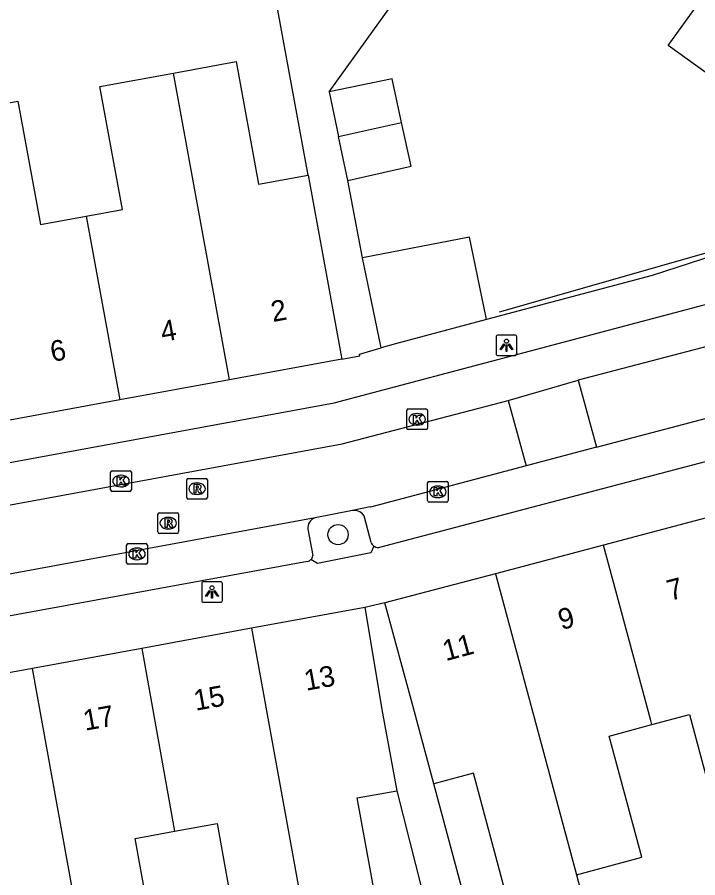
# Model space of a CAD drawing. Extents: x 159718 to 160783, y 383290 to 384030.
# Drawn here: x 160296.37 to 160329.24, y 383658.33 to 383699.92 of the extents above; entities that cross this region are included whole.
import ezdxf

# ---------------------------------------------------------------- set-up
doc = ezdxf.new("R2010")
doc.units = 0
for name, color, linetype in [('IMGEO_Boom', 7, 'Continuous'), ('IMGEO_Kolk', 7, 'Continuous'), ('IMGEO_Lichtpunt', 7, 'Continuous'), ('IMGEO_Muur', 7, 'Continuous'), ('IMGEO_Pand', 7, 'Continuous'), ('IMGEO_Pand_nummerreeks', 7, 'Continuous'), ('IMGEO_Parkeervlak_open', 7, 'Continuous'), ('IMGEO_Rijbaan_lokaal_open', 7, 'Continuous'), ('IMGEO_Rioolput', 7, 'Continuous'), ('IMGEO_Voetpad_open', 7, 'Continuous')]:
    doc.layers.add(name, color=color, linetype=linetype)

msp = doc.modelspace()

# ---------------------------------------------------------------- linework, layer by layer
at = {"layer": 'IMGEO_Boom'}
msp.add_circle((160311.869, 383674.911), 0.489, dxfattribs=at)
at = {"layer": 'IMGEO_Kolk'}
for p, q in [((160315.187, 383680.059), (160315.187, 383680.911)), ((160315.262, 383680.985), (160316.114, 383680.985)), ((160316.188, 383680.911), (160316.188, 383680.059)), ((160315.675, 383680.765), (160315.7, 383680.765)), ((160316.114, 383679.985), (160315.262, 383679.985)), ((160315.698, 383680.205), (160315.673, 383680.205)), ((160300.885, 383677.074), (160300.885, 383677.926)), ((160300.96, 383678), (160301.812, 383678)), ((160301.886, 383677.926), (160301.886, 383677.074)), ((160301.373, 383677.78), (160301.398, 383677.78)), ((160301.396, 383677.22), (160301.371, 383677.22)), ((160316.191, 383676.556), (160316.191, 383677.408)), ((160316.266, 383677.482), (160317.118, 383677.482)), ((160316.679, 383677.262), (160316.704, 383677.262)), ((160317.192, 383677.408), (160317.192, 383676.556)), ((160301.812, 383677), (160300.96, 383677)), ((160316.702, 383676.702), (160316.677, 383676.702)), ((160317.118, 383676.482), (160316.266, 383676.482)), ((160301.657, 383673.555), (160301.657, 383674.407)), ((160301.732, 383674.481), (160302.584, 383674.481)), ((160302.145, 383674.261), (160302.17, 383674.261)), ((160302.658, 383674.407), (160302.658, 383673.555)), ((160302.584, 383673.481), (160301.732, 383673.481)), ((160302.168, 383673.701), (160302.143, 383673.701))]:
    msp.add_line(p, q, dxfattribs=at)
for points in [[(160315.187, 383680.059), (160315.187, 383680.911)], [(160315.262, 383680.985), (160316.114, 383680.985)], [(160316.188, 383680.911), (160316.188, 383680.059)], [(160315.508, 383680.685), (160315.631, 383680.685), (160315.631, 383680.534), (160315.761, 383680.685), (160315.925, 383680.685), (160315.779, 383680.534), (160315.932, 383680.285), (160315.78, 383680.285), (160315.695, 383680.449), (160315.631, 383680.382), (160315.631, 383680.285), (160315.508, 383680.285), (160315.508, 383680.685)], [(160316.114, 383679.985), (160315.262, 383679.985)], [(160300.885, 383677.074), (160300.885, 383677.926)], [(160300.96, 383678), (160301.812, 383678)], [(160301.886, 383677.926), (160301.886, 383677.074)], [(160301.206, 383677.7), (160301.329, 383677.7), (160301.329, 383677.549), (160301.459, 383677.7), (160301.623, 383677.7), (160301.477, 383677.549), (160301.63, 383677.3), (160301.478, 383677.3), (160301.393, 383677.464), (160301.329, 383677.397), (160301.329, 383677.3), (160301.206, 383677.3), (160301.206, 383677.7)], [(160316.191, 383676.556), (160316.191, 383677.408)], [(160316.266, 383677.482), (160317.118, 383677.482)], [(160316.512, 383677.182), (160316.635, 383677.182), (160316.635, 383677.031), (160316.765, 383677.182), (160316.929, 383677.182), (160316.783, 383677.031), (160316.936, 383676.782), (160316.784, 383676.782), (160316.699, 383676.946), (160316.635, 383676.879), (160316.635, 383676.782), (160316.512, 383676.782), (160316.512, 383677.182)], [(160317.192, 383677.408), (160317.192, 383676.556)], [(160301.812, 383677), (160300.96, 383677)], [(160317.118, 383676.482), (160316.266, 383676.482)], [(160301.657, 383673.555), (160301.657, 383674.407)], [(160301.732, 383674.481), (160302.584, 383674.481)], [(160301.978, 383674.181), (160302.101, 383674.181), (160302.101, 383674.03), (160302.231, 383674.181), (160302.395, 383674.181), (160302.249, 383674.03), (160302.402, 383673.781), (160302.25, 383673.781), (160302.165, 383673.945), (160302.101, 383673.878), (160302.101, 383673.781), (160301.978, 383673.781), (160301.978, 383674.181)], [(160302.658, 383674.407), (160302.658, 383673.555)], [(160302.584, 383673.481), (160301.732, 383673.481)]]:
    msp.add_lwpolyline(points, dxfattribs=at)
for centre, start, end in [((160315.264, 383680.909), 91.552, 178.448), ((160315.264, 383680.909), 91.552, 178.448), ((160316.112, 383680.909), 1.552, 88.448), ((160316.112, 383680.909), 1.552, 88.448), ((160315.264, 383680.061), 181.552, 268.448), ((160315.264, 383680.061), 181.552, 268.448), ((160316.112, 383680.061), 271.552, 358.448), ((160316.112, 383680.061), 271.552, 358.448), ((160300.962, 383677.924), 91.552, 178.448), ((160300.962, 383677.924), 91.552, 178.448), ((160301.81, 383677.924), 1.552, 88.448), ((160301.81, 383677.924), 1.552, 88.448), ((160300.962, 383677.076), 181.552, 268.448), ((160300.962, 383677.076), 181.552, 268.448), ((160301.81, 383677.076), 271.552, 358.448), ((160301.81, 383677.076), 271.552, 358.448), ((160316.268, 383677.406), 91.552, 178.448), ((160316.268, 383677.406), 91.552, 178.448), ((160317.116, 383677.406), 1.552, 88.448), ((160317.116, 383677.406), 1.552, 88.448), ((160316.268, 383676.558), 181.552, 268.448), ((160316.268, 383676.558), 181.552, 268.448), ((160317.116, 383676.558), 271.552, 358.448), ((160317.116, 383676.558), 271.552, 358.448), ((160301.734, 383674.405), 91.552, 178.448), ((160301.734, 383674.405), 91.552, 178.448), ((160302.582, 383674.405), 1.552, 88.448), ((160302.582, 383674.405), 1.552, 88.448), ((160301.734, 383673.557), 181.552, 268.448), ((160301.734, 383673.557), 181.552, 268.448), ((160302.582, 383673.557), 271.552, 358.448), ((160302.582, 383673.557), 271.552, 358.448)]:
    msp.add_arc(centre, 0.0765, start, end, dxfattribs=at)
for centre, major_axis, ratio, start_param, end_param in [((160315.674, 383680.485), (-0.387, 0.002), 0.722429, 4.712389, 7.853982), ((160315.699, 383680.485), (-0.39, 0.002), 0.717154, 1.570796, 4.712389), ((160301.372, 383677.5), (-0.387, 0.002), 0.722429, 4.712389, 7.853982), ((160301.397, 383677.5), (-0.39, 0.002), 0.717154, 1.570796, 4.712389), ((160316.678, 383676.982), (-0.387, 0.002), 0.722429, 4.712389, 7.853982), ((160316.703, 383676.982), (-0.39, 0.002), 0.717154, 1.570796, 4.712389), ((160302.144, 383673.981), (-0.387, 0.002), 0.722429, 4.712389, 7.853982), ((160302.169, 383673.981), (-0.39, 0.002), 0.717154, 1.570796, 4.712389)]:
    msp.add_ellipse(centre, major_axis=major_axis, ratio=ratio, start_param=start_param, end_param=end_param, dxfattribs=at)
at = {"layer": 'IMGEO_Lichtpunt'}
for p, q in [((160320.408, 383684.558), (160319.6, 383684.558)), ((160320.408, 383684.558), (160319.6, 383684.558)), ((160319.506, 383684.463), (160319.506, 383683.656)), ((160319.506, 383684.463), (160319.506, 383683.656)), ((160320.502, 383683.656), (160320.502, 383684.463)), ((160320.502, 383683.656), (160320.502, 383684.463)), ((160319.6, 383683.562), (160320.408, 383683.562)), ((160319.6, 383683.562), (160320.408, 383683.562)), ((160305.285, 383672.544), (160305.285, 383671.737)), ((160305.285, 383672.544), (160305.285, 383671.737)), ((160306.187, 383672.639), (160305.379, 383672.639)), ((160306.187, 383672.639), (160305.379, 383672.639)), ((160306.281, 383671.737), (160306.281, 383672.544)), ((160306.281, 383671.737), (160306.281, 383672.544)), ((160305.379, 383671.643), (160306.187, 383671.643)), ((160305.379, 383671.643), (160306.187, 383671.643))]:
    msp.add_line(p, q, dxfattribs=at)
for points in [[(160319.88, 383684.127), (160319.919, 383684.099), (160319.731, 383683.837), (160319.693, 383683.864), (160319.88, 383684.127)], [(160319.982, 383684.079), (160320.029, 383684.079), (160320.029, 383683.757), (160319.982, 383683.757), (160319.982, 383684.079)], [(160320.092, 383684.099), (160320.13, 383684.126), (160320.317, 383683.864), (160320.278, 383683.836), (160320.092, 383684.099)], [(160305.659, 383672.208), (160305.698, 383672.18), (160305.51, 383671.918), (160305.472, 383671.945), (160305.659, 383672.208)], [(160305.761, 383672.16), (160305.808, 383672.16), (160305.808, 383671.838), (160305.761, 383671.838), (160305.761, 383672.16)], [(160305.871, 383672.18), (160305.909, 383672.207), (160306.096, 383671.945), (160306.057, 383671.917), (160305.871, 383672.18)]]:
    msp.add_lwpolyline(points, dxfattribs=at)
for centre in [(160320.005, 383684.261), (160305.784, 383672.342)]:
    msp.add_circle(centre, 0.0994, dxfattribs=at)
for centre, start, end in [((160319.6, 383684.463), 90, 180), ((160319.6, 383684.463), 90, 180), ((160320.408, 383684.463), 0, 90), ((160320.408, 383684.463), 0, 90), ((160319.6, 383683.656), 180, 270), ((160319.6, 383683.656), 180, 270), ((160320.408, 383683.656), 270, 0), ((160320.408, 383683.656), 270, 360), ((160305.379, 383672.544), 90, 180), ((160305.379, 383672.544), 90, 180), ((160306.187, 383672.544), 0, 90), ((160306.187, 383672.544), 0, 90), ((160305.379, 383671.737), 180, 270), ((160305.379, 383671.737), 180, 270), ((160306.187, 383671.737), 270, 0), ((160306.187, 383671.737), 270, 360)]:
    msp.add_arc(centre, 0.0946, start, end, dxfattribs=at)
at = {"layer": 'IMGEO_Muur'}
msp.add_lwpolyline([(160330.189, 383688.675), (160319.647, 383685.659)], dxfattribs=at)
at = {"layer": 'IMGEO_Pand'}
for points in [[(160330.562, 383696.566), (160327.807, 383698.555), (160331.167, 383703.206), (160329.688, 383704.274)], [(160303.92, 383697.218), (160306.948, 383697.772), (160308.033, 383691.84), (160310.427, 383692.278)], [(160299.702, 383690.309), (160301.457, 383690.63), (160300.37, 383696.568), (160303.92, 383697.218)], [(160306.633, 383682.393), (160303.92, 383697.218)], [(160314.94, 383694.825), (160314.477, 383696.939), (160311.443, 383696.314)], [(160311.443, 383696.314), (160311.892, 383694.157)], [(160293.306, 383695.296), (160296.401, 383695.862), (160297.492, 383689.904), (160299.702, 383690.309)], [(160311.892, 383694.157), (160314.94, 383694.825)], [(160312.335, 383692.03), (160315.403, 383692.711), (160314.94, 383694.825)], [(160312.335, 383692.03), (160311.892, 383694.157)], [(160310.427, 383692.278), (160311.153, 383688.319), (160312.009, 383683.641), (160312.056, 383683.385)], [(160299.702, 383690.309), (160301.328, 383681.422)], [(160319.035, 383685.301), (160319, 383685.474), (160318.226, 383689.286), (160313.049, 383688.282)], [(160313.952, 383683.934), (160313.933, 383684.025), (160313.049, 383688.282)], [(160319.035, 383685.301), (160314.651, 383684.131), (160313.952, 383683.934)], [(160312.056, 383683.385), (160306.633, 383682.393)], [(160306.633, 383682.393), (160301.328, 383681.422)], [(160301.328, 383681.422), (160296.023, 383680.451)], [(160329.908, 383675.785), (160324.693, 383674.405)], [(160324.693, 383674.405), (160319.475, 383673.025)], [(160327.021, 383665.734), (160326.969, 383665.926), (160324.693, 383674.405)], [(160319.475, 383673.025), (160314.123, 383671.61)], [(160319.475, 383673.025), (160323.384, 383658.474)], [(160313.168, 383671.395), (160307.692, 383670.389)], [(160313.168, 383671.395), (160314.023, 383666.285), (160314.702, 383662.535)], [(160316.493, 383662.865), (160315.492, 383666.591), (160314.123, 383671.61)], [(160307.692, 383670.389), (160302.397, 383669.416)], [(160307.692, 383670.389), (160310.354, 383655.668)], [(160302.397, 383669.416), (160297.104, 383668.443)], [(160302.397, 383669.416), (160303.973, 383660.578)], [(160297.104, 383668.443), (160291.809, 383667.47)], [(160299.764, 383653.735), (160297.104, 383668.443)], [(160327.021, 383665.734), (160328.843, 383666.223), (160330.426, 383660.326), (160333.816, 383661.236)], [(160323.384, 383658.474), (160326.535, 383659.32), (160324.961, 383665.181), (160327.021, 383665.734)], [(160323.384, 383658.474), (160323.989, 383656.22), (160320.586, 383655.306), (160319.981, 383657.56), (160318.418, 383663.382), (160316.493, 383662.865)], [(160310.354, 383655.668), (160313.865, 383656.303), (160312.8, 383662.191), (160314.702, 383662.535)], [(160303.973, 383660.578), (160306.028, 383660.95), (160306.971, 383655.733), (160307.128, 383655.084), (160310.354, 383655.668)], [(160299.764, 383653.735), (160303.131, 383654.344), (160302.065, 383660.233), (160303.973, 383660.578)]]:
    msp.add_lwpolyline(points, dxfattribs=at)
at = {"layer": 'IMGEO_Parkeervlak_open'}
for points in [[(160313.463, 383674.524), (160313.153, 383675.759)], [(160310.415, 383675.17), (160310.647, 383673.9)]]:
    msp.add_lwpolyline(points, dxfattribs=at)
for centre, radius, start, end in [((160312.657, 383675.539), 0.543, 23.8999, 99.1826), ((160310.914, 383675.243), 0.505, 107.6978, 188.3286), ((160313.858, 383674.714), 0.438, 205.7062, 233.4862), ((160310.317, 383673.93), 0.332, 317.6925, 354.7687)]:
    msp.add_arc(centre, radius, start, end, dxfattribs=at)
at = {"layer": 'IMGEO_Rijbaan_lokaal_open'}
for points in [[(160343.917, 383687.725), (160323.47, 383682.384)], [(160320.087, 383681.393), (160323.47, 383682.384)], [(160323.47, 383682.384), (160324.345, 383679.14)], [(160268.529, 383671.299), (160312.074, 383679.307), (160320.087, 383681.393)], [(160320.087, 383681.393), (160320.96, 383678.239)], [(160324.345, 383679.14), (160330.346, 383680.717)], [(160324.345, 383679.14), (160320.96, 383678.239)], [(160320.96, 383678.239), (160313.442, 383676.239), (160313.418, 383676.249), (160312.57, 383676.075)], [(160312.57, 383676.075), (160310.761, 383675.724)], [(160310.761, 383675.724), (160292.67, 383672.382)]]:
    msp.add_lwpolyline(points, dxfattribs=at)
at = {"layer": 'IMGEO_Rioolput'}
for p, q in [((160304.559, 383676.706), (160304.559, 383677.558)), ((160304.634, 383677.632), (160305.486, 383677.632)), ((160305.56, 383677.558), (160305.56, 383676.706)), ((160305.047, 383677.412), (160305.072, 383677.412)), ((160305.07, 383676.852), (160305.045, 383676.852)), ((160305.486, 383676.632), (160304.634, 383676.632)), ((160303.168, 383675.042), (160303.168, 383675.894)), ((160303.243, 383675.968), (160304.095, 383675.968)), ((160304.169, 383675.894), (160304.169, 383675.042)), ((160303.656, 383675.748), (160303.681, 383675.748)), ((160303.679, 383675.188), (160303.654, 383675.188)), ((160304.095, 383674.968), (160303.243, 383674.968))]:
    msp.add_line(p, q, dxfattribs=at)
for points in [[(160304.559, 383676.706), (160304.559, 383677.558)], [(160304.634, 383677.632), (160305.486, 383677.632)], [(160305.56, 383677.558), (160305.56, 383676.706)], [(160305.148, 383677.33), (160304.896, 383677.332), (160304.896, 383676.932)], [(160304.896, 383676.932), (160305.02, 383676.932), (160305.02, 383677.094), (160305.031, 383677.094)], [(160305.074, 383677.251), (160305.02, 383677.251), (160305.02, 383677.17)], [(160305.02, 383677.17), (160305.072, 383677.17)], [(160305.078, 383677.065), (160305.149, 383676.932), (160305.289, 383676.932), (160305.224, 383677.058)], [(160305.486, 383676.632), (160304.634, 383676.632)], [(160303.168, 383675.042), (160303.168, 383675.894)], [(160303.243, 383675.968), (160304.095, 383675.968)], [(160304.169, 383675.894), (160304.169, 383675.042)], [(160303.757, 383675.666), (160303.505, 383675.668), (160303.505, 383675.268)], [(160303.505, 383675.268), (160303.629, 383675.268), (160303.629, 383675.43), (160303.64, 383675.43)], [(160303.683, 383675.587), (160303.629, 383675.587), (160303.629, 383675.506)], [(160303.629, 383675.506), (160303.681, 383675.506)], [(160303.687, 383675.401), (160303.758, 383675.268), (160303.898, 383675.268), (160303.833, 383675.394)], [(160304.095, 383674.968), (160303.243, 383674.968)]]:
    msp.add_lwpolyline(points, dxfattribs=at)
for centre, radius, start, end in [((160304.636, 383677.556), 0.0765, 91.552, 178.448), ((160304.636, 383677.556), 0.0765, 91.552, 178.448), ((160305.484, 383677.556), 0.0765, 1.552, 88.448), ((160305.484, 383677.556), 0.0765, 1.552, 88.448), ((160305.03, 383677.041), 0.0533, 26.0293, 88.6989), ((160305.056, 383677.359), 0.19, 274.7715, 282.9687), ((160305.08, 383677.155), 0.0964, 77.0061, 93.1865), ((160305.094, 383677.212), 0.0378, 276.6634, 79.6772), ((160305.147, 383677.22), 0.109, 350.3612, 89.416), ((160305.145, 383677.22), 0.112, 277.5842, 350.9817), ((160305.129, 383677.005), 0.108, 29.5134, 73.7905), ((160304.636, 383676.708), 0.0765, 181.552, 268.448), ((160304.636, 383676.708), 0.0765, 181.552, 268.448), ((160305.484, 383676.708), 0.0765, 271.552, 358.448), ((160305.484, 383676.708), 0.0765, 271.552, 358.448), ((160303.245, 383675.892), 0.0765, 91.552, 178.448), ((160303.245, 383675.892), 0.0765, 91.552, 178.448), ((160304.093, 383675.892), 0.0765, 1.552, 88.448), ((160304.093, 383675.892), 0.0765, 1.552, 88.448), ((160303.639, 383675.377), 0.0533, 26.0293, 88.6989), ((160303.665, 383675.695), 0.19, 274.7715, 282.9687), ((160303.689, 383675.491), 0.0964, 77.0061, 93.1865), ((160303.703, 383675.548), 0.0378, 276.6634, 79.6772), ((160303.756, 383675.556), 0.109, 350.3612, 89.416), ((160303.754, 383675.556), 0.112, 277.5842, 350.9817), ((160303.738, 383675.341), 0.108, 29.5134, 73.7905), ((160303.245, 383675.044), 0.0765, 181.552, 268.448), ((160303.245, 383675.044), 0.0765, 181.552, 268.448), ((160304.093, 383675.044), 0.0765, 271.552, 358.448), ((160304.093, 383675.044), 0.0765, 271.552, 358.448)]:
    msp.add_arc(centre, radius, start, end, dxfattribs=at)
for centre, major_axis, ratio, start_param, end_param in [((160305.046, 383677.132), (-0.387, 0.002), 0.722429, 4.712389, 7.853982), ((160305.071, 383677.132), (-0.39, 0.002), 0.717154, 1.570796, 4.712389), ((160303.655, 383675.468), (-0.387, 0.002), 0.722429, 4.712389, 7.853982), ((160303.68, 383675.468), (-0.39, 0.002), 0.717154, 1.570796, 4.712389)]:
    msp.add_ellipse(centre, major_axis=major_axis, ratio=ratio, start_param=start_param, end_param=end_param, dxfattribs=at)
at = {"layer": 'IMGEO_Voetpad_open'}
for points in [[(160311.443, 383696.314), (160321.541, 383710.348)], [(160310.427, 383692.278), (160308.85, 383700.877), (160306.133, 383702.705)], [(160313.049, 383688.282), (160312.335, 383692.03)], [(160337.621, 383690.859), (160330.794, 383688.651), (160330.061, 383688.414), (160327.047, 383687.439), (160319.035, 383685.301)], [(160243.738, 383668.782), (160311.679, 383681.281), (160321.168, 383683.787), (160342.669, 383689.488)], [(160312.056, 383683.385), (160312.924, 383683.546), (160312.906, 383683.638), (160313.952, 383683.934)], [(160330.213, 383678.586), (160313.812, 383674.281)], [(160313.597, 383674.362), (160313.446, 383674.031), (160310.883, 383673.523), (160310.562, 383673.707)], [(160310.394, 383673.609), (160293.746, 383670.571)], [(160314.123, 383671.61), (160313.168, 383671.395)], [(160314.702, 383662.535), (160318.637, 383647.018), (160319.332, 383644.202), (160318.989, 383644.117)], [(160328.545, 383646.613), (160321.361, 383644.745), (160316.493, 383662.865)]]:
    msp.add_lwpolyline(points, dxfattribs=at)
for centre, radius, start, end in [((160313.852, 383674.712), 0.433, 233.9797, 264.7331), ((160310.32, 383673.928), 0.328, 282.9996, 317.5133)]:
    msp.add_arc(centre, radius, start, end, dxfattribs=at)

# ---------------------------------------------------------------- texts
at = {"layer": 'IMGEO_Pand_nummerreeks'}
for s, rotation, p in [('2', 10.2502, (160308.722, 383685.184)), ('4', 10.2502, (160303.393, 383684.219)), ('6', 10.2502, (160298.063, 383683.255)), ('7', 15.0344, (160327.906, 383671.705)), ('9', 15.0344, (160322.656, 383670.295)), ('11', 15.0344, (160317.071, 383668.795)), ('13', 10.2559, (160310.326, 383667.364)), ('15', 10.2559, (160304.99, 383666.398)), ('17', 10.2559, (160299.655, 383665.433))]:
    msp.add_text(s, height=1, rotation=rotation, dxfattribs=at).set_placement(p)

doc.saveas('drawing.dxf')
